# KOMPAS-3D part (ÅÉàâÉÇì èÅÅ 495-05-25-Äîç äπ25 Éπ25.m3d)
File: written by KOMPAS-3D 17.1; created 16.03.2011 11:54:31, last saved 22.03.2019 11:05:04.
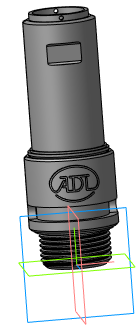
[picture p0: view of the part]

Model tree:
1. Плоскость XY
2. Плоскость ZX
3. Плоскость ZY
4. Ось X
5. Ось Y
6. Ось Z
7. Начало координат
8. Операция без истории:2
